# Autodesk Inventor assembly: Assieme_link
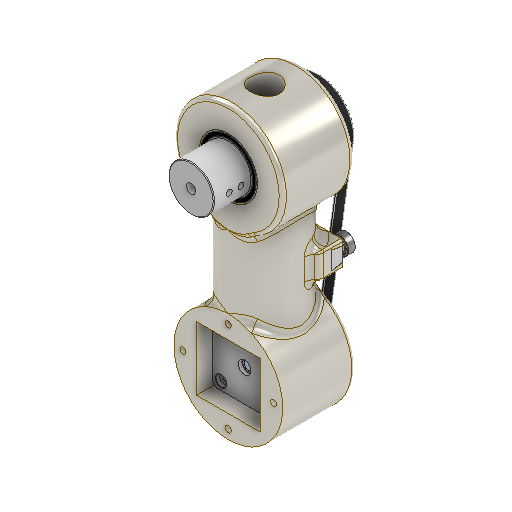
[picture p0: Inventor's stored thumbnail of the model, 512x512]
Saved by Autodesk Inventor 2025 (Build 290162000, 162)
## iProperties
Created: 2025-05
Part Number: Assieme_link
Document SubType Name: Assembly
Designer: 18907419
Author: 18907419
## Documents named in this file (9)
- C:\Users\R5800u\Desktop\robot v3\Assieme_link.iam
- C:\Users\R5800u\Desktop\robot v3\NEMA_14-13mm.iam
- C:\Users\R5800u\Desktop\robot v3\blocco3.ipt
- C:\Users\R5800u\Desktop\robot v3\gt2-60.ipt
- C:\Users\R5800u\Desktop\robot v3\cinghia.ipt
- C:\Users\R5800u\Desktop\robot v3\blocco_tendi.ipt
- C:\Users\R5800u\Documents\Inventor\Content Center Files\R2025\it-IT\BS 290 SKF(30)\BS 290 SKF - SKF 623.ipt
- C:\Users\R5800u\Desktop\robot v3\6705-2RS.ipt
- C:\Users\R5800u\Documents\Inventor\Content Center Files\R2025\it-IT\AS 1420\AS 1420 - 1973 - M3 x 6.ipt
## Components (9 placed, 8 different names)
1. blocco3:2 — Coincidente:64, Allineato:11, Coincidente:65, Coincidente:66, Coincidente:67, Allineato:14, Rotazionale:25, Rotazionale:26, Coincidente:74, Rigido:1, Angolo:1
2. NEMA_14HM11-0404S:4 [sub-assembly] — Coincidente:66, Coincidente:67, Coincidente:73, Allineato:15
3. cinghia:1 — Coincidente:73, Coincidente:76, Allineato:16
4. blocco_tendi:1 — Allineato:14, Rigido:1, Rotazionale:27
5. 6705-2RS:3 — Rotazionale:25
6. 6705-2RS:4 — Rotazionale:26, Coincidente:75
7. gt2-60:1 — Coincidente:74, Coincidente:75, Allineato:15, Coincidente:76, Angolo:1, Allineato:16
8. BS 290 SKF 623:1 — Rotazionale:27
9. AS 1420 - Metrico M3 x 6:1
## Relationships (17: Mate 8, Flush 4, RevoluteJoint 3, WeldJoint 1, Angle 1)
- Coincidente:64 [Mate]: blocco3:2
- Allineato:11 [Flush]: blocco3:2
- Coincidente:65 [Mate]: blocco3:2
- Coincidente:66 [Mate]: blocco3:2 ↔ NEMA_14HM11-0404S:4
- Coincidente:67 [Mate]: blocco3:2 ↔ NEMA_14HM11-0404S:4
- Allineato:14 [Flush]: blocco3:2 ↔ blocco_tendi:1
- Rotazionale:25 [RevoluteJoint]: blocco3:2 ↔ 6705-2RS:3
- Coincidente:73 [Mate]: NEMA_14HM11-0404S:4 ↔ cinghia:1
- Rotazionale:26 [RevoluteJoint]: blocco3:2 ↔ 6705-2RS:4
- Coincidente:74 [Mate]: blocco3:2 ↔ gt2-60:1
- Coincidente:75 [Mate]: 6705-2RS:4 ↔ gt2-60:1
- Allineato:15 [Flush]: NEMA_14HM11-0404S:4 ↔ gt2-60:1
- Coincidente:76 [Mate]: cinghia:1 ↔ gt2-60:1
- Rigido:1 [WeldJoint]: blocco3:2 ↔ blocco_tendi:1
- Angolo:1 [Angle]: blocco3:2 ↔ gt2-60:1
- Allineato:16 [Flush]: cinghia:1 ↔ gt2-60:1
- Rotazionale:27 [RevoluteJoint]: blocco_tendi:1 ↔ BS 290 SKF 623:1
